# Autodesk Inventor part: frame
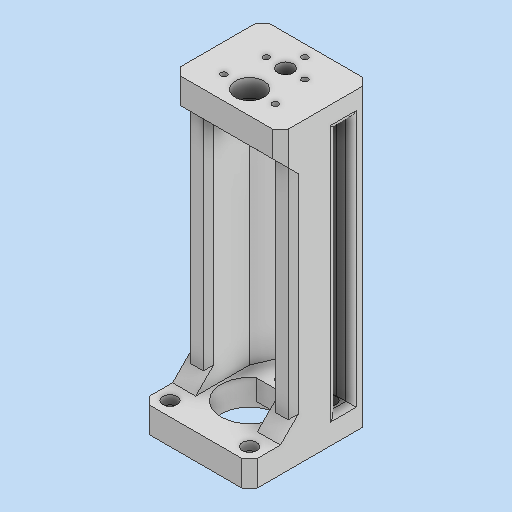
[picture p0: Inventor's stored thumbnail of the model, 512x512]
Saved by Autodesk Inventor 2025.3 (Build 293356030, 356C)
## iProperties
Created: 2025-12
Part Number: frame
Material: Generico
Document SubType Name: Modeling
Designer: Ryzen5700u
Density: 1 g/cm^3
Appearance: Default
Author: Ryzen5700u
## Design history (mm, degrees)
node "Piano di lavoro1"
sketch "Schizzo1"
  geometry: L1 (-0.604, 21)-(41.396, 21); L2 (41.396, 21)-(41.396, -21); L3 (41.396, -21)-(-0.604, -21); L4 (-0.604, -21)-(-0.604, 21); L5 (-0.604, 21)-(41.396, -21); L6 (41.396, 21)-(-0.604, -21); L7 (20.396, 0)-(20.396, -21); L8 (9.346, 0)-(9.346, 21); L9 (31.446, 0)-(31.446, 21); L10 (17.904, -15.759)-(11.328, -6.314); L11 (22.87, -15.784)-(29.464, -6.314); L12 (13.985, -9)-(26.807, -9); C1 r 1.8 at (20.396, 0) reference; C2 r 1.25 at (4.896, 15.5) reference; C3 r 1.25 at (35.896, 15.5) reference; C4 r 1.25 at (4.896, -15.5) reference; C5 r 1.25 at (35.896, -15.5) reference; C6 r 3.05 at (20.396, -14); C7 r 8 at (20.396, 0); A1 r 11.05 centre (20.396, 0) between (9.346, 0) and (31.446, 0); 5 further points
  constraints: 24 end point, 6 point on circle, 6 tangent, 3 centre point, 3 midpoint, 3 perpendicular, 3 point on line, 2 coincident, 2 horizontal, 2 parallel
  dimensions: "d0" = 42 distance of L2.end L3.end; "d1" = 42 distance of L1.end L2.end; "d2" = 22.1 diameter of A1; "d3" = 6.1 diameter of C6; "d4" = 14 distance of C1.centre C6.centre; "d7" = 16 diameter of C7; "d8" = 12 distance between parallel lines of L3 L12
extrude "Estrusione1" new body sketch "Schizzo1" distance "d5" = 10; taper "d6" = 0 deg
sketch "Schizzo2"
  geometry: C1 r 3.05 at (20.396, -14) reference; C2 r 2.258 at (20.396, -14); C3 r 1 at (20.396, -14); 1 further point
  constraints: 2 centre point, 2 coincident
  dimensions: "d9" = 2 diameter of C3
extrude "Estrusione2" join sketch "Schizzo2" distance "d10" = 7; taper "d11" = 0 deg
sketch "Schizzo3"
  geometry: C1 r 3.05 at (20.396, -14) reference; C2 r 1.6 at (20.396, -14); 1 further point
  constraints: 1 centre point, 1 coincident
  dimensions: "d12" = 3.2 diameter of C2
extrude "Estrusione3" join sketch "Schizzo3" distance "d13" = 7; taper "d14" = 0 deg
sketch "Schizzo4"
  geometry: L1 (26.807, 9)-(13.985, 9) reference; L2 (41.396, -21)-(-0.604, -21) reference; L3 (41.396, 21)-(41.396, -21) reference; L4 (-0.604, 21)-(41.396, 21) reference; L5 (-0.604, -21)-(-0.604, 21) reference; L6 (14.396, 16)-(14.396, 10) reference; L7 (14.396, 10)-(12.396, 10) reference; L8 (10.396, 8)-(10.396, -10) reference; L9 (10.396, -10)-(30.396, -10) reference; L10 (30.396, -10)-(30.396, 8) reference; L11 (28.396, 10)-(26.396, 10) reference; L12 (26.396, 10)-(26.396, 16) reference; L13 (41.396, -4)-(-0.604, -4); L14 (32.396, 12)-(8.396, 12); L15 (8.396, 12)-(8.396, -12); L16 (8.396, -12)-(32.396, -12); L17 (32.396, -12)-(32.396, 12); L18 (32.396, 12)-(8.396, -12); L19 (8.396, 12)-(32.396, -12); L20 (20.396, 14)-(20.396, 19); L21 (20.396, 19)-(11.396, 19); L22 (11.396, 19)-(8.396, 12); L23 (20.396, 19)-(29.396, 19); L24 (29.396, 19)-(32.396, 12); C1 r 1.25 at (4.896, -15.5) reference; C2 r 1.25 at (35.896, -15.5) reference; C3 r 1.25 at (4.896, 15.5) reference; C4 r 1.25 at (35.896, 15.5) reference; C5 r 2.25 at (20.396, 0) reference; C6 r 1.23 at (20.396, 6.5) reference; C7 r 1.23 at (14.767, -3.25) reference; C8 r 1.23 at (26.025, -3.25) reference; C9 r 3.05 at (20.396, 14) reference; C10 r 9.8 at (20.396, 0) reference; C11 r 1.6 at (20.396, 14) reference; A1 r 11.05 centre (20.396, 0) between (13.985, 9) and (26.807, 9) reference; A2 r 2 centre (28.396, 8) between (30.396, 8) and (28.396, 10) reference; A3 r 2 centre (24.396, 16) between (26.396, 16) and (24.396, 18) reference; A4 r 2 centre (16.396, 16) between (16.396, 18) and (14.396, 16) reference; A5 r 2 centre (12.396, 8) between (12.396, 10) and (10.396, 8) reference; 11 further points
  constraints: 24 end point, 3 perpendicular, 3 point on line, 2 midpoint, 2 parallel, 1 horizontal, 1 vertical
  dimensions: "d18" = 25 distance between parallel lines of L4 L13; "d39" = 24 distance of L16.end L15.end; "d40" = 24 distance of L15.end L14.end; "d42" = 5 distance of L20.start L20.end; "d43" = 9 distance of L20.end L21.end; "d44" = 9 distance of L20.end L23.end
extrude "Estrusione4" join sketch "Schizzo4" distance "d15" = 95; taper "d16" = 0 deg
sketch "Schizzo5"
  geometry: L1 (-0.604, 21)-(41.396, 21) reference; L2 (-0.604, -21)-(-0.604, 21) reference; L3 (41.396, 21)-(-0.604, 21); L4 (-0.604, 21)-(-0.604, -21); L5 (-0.604, -21)-(41.396, -21); L6 (41.396, -21)-(41.396, 21); L7 (-0.604, -4)-(41.396, -4) reference; L8 (41.396, -4)-(-0.604, -4); L9 (41.396, -9)-(-0.604, -9); C1 r 1.6 at (20.396, 14) reference; C2 r 3.05 at (20.396, 14); 6 further points
  constraints: 12 end point, 3 perpendicular, 3 point on line, 2 parallel, 1 centre point, 1 coincident, 1 horizontal, 1 midpoint
  dimensions: "d19" = 6.1 diameter of C2; "d22" = 5 distance from line of L8 point (20.396, -9)
extrude "Estrusione5" join sketch "Schizzo5" distance "d20" = 10; taper "d21" = 0 deg
sketch "Schizzo6"
  geometry: C1 r 2.25 at (20.396, 0) reference; 1 further point
hole "Foro1" sketch "Schizzo6" at (20.396, 0) diameter "d23" = 11.1; stored, may be unused: countersink angle "d27" = 90 deg, drill point angle "d29" = 118 deg; dims "d24" = 8, "d25" = 4, "d26" = 2, "d28" = 11.8
chamfer "Smusso1" distance "d30" = 5; stored, may be unused: second distance "d31" = 2, angle "d32" = 45 deg
chamfer "Smusso2" distance "d33" = 3; stored, may be unused: second distance "d34" = 2, angle "d35" = 45 deg
sketch "Schizzo7"
  geometry: C1 r 4 at (20.396, 0); 4 further points
  constraints: 1 centre point, 1 coincident, 1 other
  dimensions: "d36" = 8 diameter of C1
extrude "Estrusione6" join sketch "Schizzo7" distance "d37" = 3; taper "d38" = 0 deg
sketch "Schizzo8"
  geometry: L1 (0, 115)-(0, 0) reference; L2 (42, 0)-(0, 0) reference; L3 (42, 115)-(42, 0) reference; L4 (0, 115)-(42, 115) reference; 1 further point
extrude "Estrusione7" join sketch "Schizzo8" distance "d45" = 5; taper "d46" = 0 deg
chamfer "Smusso3" distance "d47" = 3; stored, may be unused: second distance "d48" = 2, angle "d49" = 45 deg
sketch "Schizzo9"
  geometry: L1 (35.896, 12.5)-(41.465, 12.5); L2 (35.896, 18.5)-(41.465, 18.5); L3 (4.896, 12.5)-(-0.604, 12.5); L4 (-0.604, -18)-(-0.604, 23) reference; L5 (4.896, 18.5)-(-0.604, 18.5); L6 (41.396, -18)-(41.396, 23) reference; C1 r 1.25 at (35.896, 15.5) reference; C2 r 1.25 at (4.896, 15.5) reference; A1 r 3 centre (35.896, 15.5) between (35.896, 12.5) and (35.896, 18.5); A2 r 3 centre (4.896, 15.5) between (4.896, 12.5) and (4.896, 18.5); 3 further points
  constraints: 8 end point, 4 point on circle, 3 horizontal, 3 tangent, 2 centre point, 2 coincident, 2 point on line, 1 perpendicular
  dimensions: "d50" = 6 diameter of A1; "d51" = 6 diameter of A2
extrude "Estrusione8" cut sketch "Schizzo9" distance "d52" = 96; taper "d53" = 0 deg
sketch "Schizzo10"
  geometry: C1 r 1.25 at (4.896, 15.5) reference; 2 further points
  constraints: 1 coincident
hole "Foro2" sketch "Schizzo10" at (4.896, 15.5) diameter "d54" = 3.4; stored, may be unused: countersink angle "d58" = 82 deg, drill point angle "d60" = 118 deg; dims "d55" = 6, "d56" = 5.5, "d57" = 3.4, "d59" = 11.8
sketch "Schizzo11"
  geometry: C1 r 1.25 at (35.896, 15.5) reference; 2 further points
  constraints: 1 coincident
hole "Foro3" sketch "Schizzo11" at (35.896, 15.5) diameter "d61" = 3.4; stored, may be unused: countersink angle "d65" = 90 deg, drill point angle "d67" = 118 deg; dims "d62" = 6, "d63" = 5.5, "d64" = 3.4, "d66" = 11.8
fillet "Raccordo1" dims "d68" = 2
sketch "Schizzo12"
  geometry: L1 (15.896, -9.5)-(24.896, -9.5); L2 (24.896, -9.5)-(24.896, -18.5); L3 (24.896, -18.5)-(15.896, -18.5); L4 (15.896, -18.5)-(15.896, -9.5); L5 (15.896, -9.5)-(24.896, -18.5); L6 (24.896, -9.5)-(15.896, -18.5); L7 (2.396, -26)-(38.396, -26) reference; L8 (15.896, -18.5)-(24.896, -18.5); L9 (24.896, -18.5)-(24.896, -26); L10 (24.896, -26)-(15.896, -26); L11 (15.896, -26)-(15.896, -18.5); C1 r 3.05 at (20.396, -14) reference; C2 r 3.05 at (20.396, -14); 3 further points
  constraints: 20 end point, 4 parallel, 2 horizontal, 2 midpoint, 2 perpendicular, 1 centre point, 1 coincident, 1 point on line
  dimensions: "d69" = 9 distance of L2.end L3.end; "d70" = 9 distance of L1.end L2.end
extrude "Estrusione9" join sketch "Schizzo12" distance "d71" = 2; taper "d72" = 0 deg
sketch "Schizzo13"
  geometry: C1 r 1.25 at (35.896, -15.5) reference; C2 r 1.25 at (4.896, -15.5) reference; 3 further points
  constraints: 2 coincident
hole "Foro4" sketch "Schizzo13" at (35.896, -15.5), (4.896, -15.5) diameter "d73" = 3.4; stored, may be unused: countersink angle "d77" = 90 deg, drill point angle "d79" = 118 deg; dims "d74" = 6, "d75" = 5.6, "d76" = 3.4, "d78" = 11.8
sketch "Schizzo14"
  geometry: C1 r 1.6 at (20.396, -14) reference; 2 further points
  constraints: 1 coincident
hole "Foro5" sketch "Schizzo14" at (20.396, -14) diameter "d80" = 4.5; stored, may be unused: countersink angle "d84" = 90 deg, drill point angle "d86" = 118 deg; dims "d81" = 6, "d82" = 7, "d83" = 4, "d85" = 11.8
sketch "Schizzo15"
  geometry: L1 (20.396, 14)-(12.896, 14); L2 (15.896, 19)-(15.896, 9.5) reference; L3 (20.396, 14)-(27.896, 14); L4 (20.396, 14)-(20.396, 21.5); C1 r 2.25 at (20.396, 14) reference; C2 r 3.5 at (20.396, 14) reference; C3 r 3.05 at (20.396, 14) reference; C4 r 5.55 at (20.396, 0) reference; A1 r 7.5 centre (20.396, 14) between (12.896, 14) and (27.896, 14); A2 r 10 centre (20.396, 0) between (30.396, 0) and (10.396, 0); 1 further point
  constraints: 6 end point, 5 point on circle, 2 centre point, 2 coincident, 1 horizontal, 1 perpendicular, 1 vertical
  dimensions: "d87" = 15 diameter of A1; "d105" = 20 diameter of A2
hole "Foro6" sketch "Schizzo15" at (20.396, 21.5), (27.896, 14), (12.896, 14), (30.396, 0), (10.396, 0) diameter "d88" = 2.4; stored, may be unused: countersink angle "d92" = 82 deg, drill point angle "d94" = 118 deg; dims "d89" = 12, "d90" = 3.023, "d91" = 2, "d93" = 8
chamfer "Smusso4" distance "d95" = 2; stored, may be unused: second distance "d96" = 2, angle "d97" = 45 deg
sketch "Schizzo16"
  geometry: C1 r 11.05 at (20.396, 0); A1 r 11.05 centre (20.396, 0) between (26.807, -9) and (13.985, -9) reference; 3 further points
  constraints: 1 centre point, 1 coincident
  dimensions: "d98" = 22.1 diameter of C1
extrude "Estrusione10" cut sketch "Schizzo16" distance "d99" = 2; taper "d100" = 0 deg
sketch "Schizzo17"
  geometry: C1 r 11.05 at (20.396, 0); C2 r 3.5 at (20.396, -14) reference; C3 r 3.5 at (20.396, -14); A1 r 11.05 centre (20.396, 0) between (26.807, -9) and (13.985, -9) reference; 3 further points
  constraints: 2 centre point, 2 coincident
extrude "Estrusione11" join sketch "Schizzo17" stored distance "d101" = 10; taper "d102" = 0 deg
sketch "Schizzo19"
  geometry: C1 r 3.05 at (20.396, 14) reference; 1 further point
extrude "Estrusione12" cut sketch "Schizzo19" distance "d103" = 6; taper "d104" = 0 deg
node "Solido1"
node "Riferimento1"
node "Riferimento2"
node "Riferimento3"
node "Riferimento4"
node "Riferimento5"
node "Linea chiusa proiettata1"
node "Riferimento7"
node "Riferimento8"
node "Linea chiusa proiettata2"
